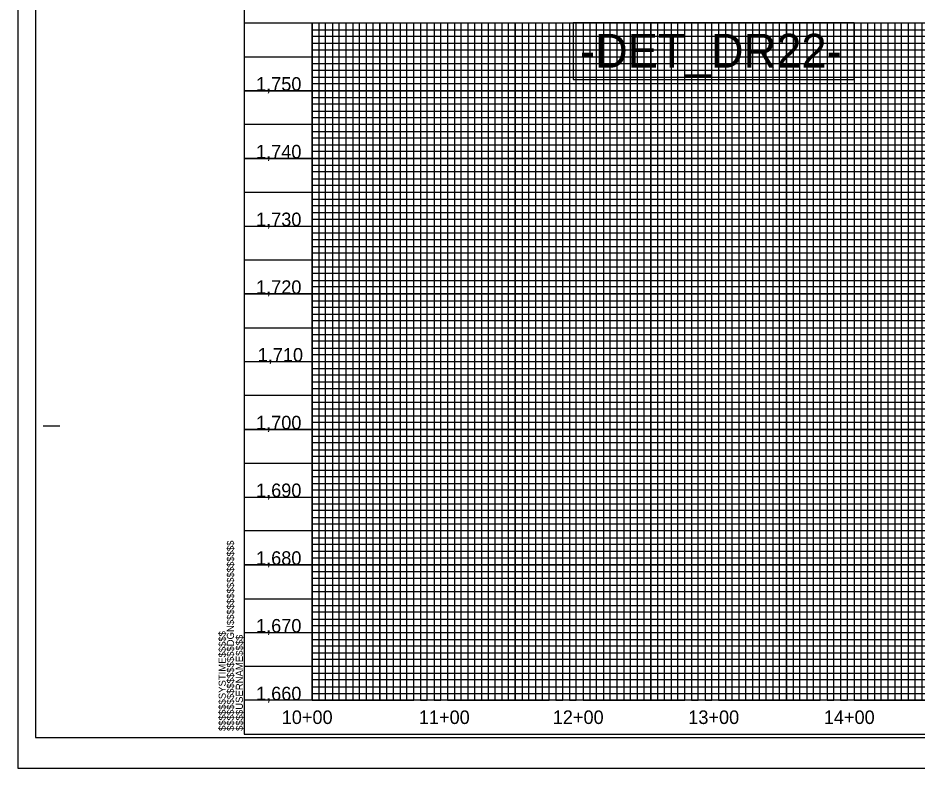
# Model space of a CAD drawing. Extents: x 505692 to 527456, y 415959 to 439886.
# Drawn here: x 505692 to 506355, y 438761 to 439315 of the extents above; entities that cross this region are included whole.
import ezdxf

# ---------------------------------------------------------------- set-up
doc = ezdxf.new("R2010")
doc.units = 0
for name, color, linetype in [('Exist Vertical Profile Vertical Axis Label', 7, 'Continuous'), ('Old_Level_1', 7, 'Continuous'), ('Prop Grid Mask', 7, 'Continuous'), ('Sheet Cutting Line CELL', 7, 'Continuous'), ('Sheet DOT Grid CELL', 7, 'Continuous'), ('Sheet Layout Profile Border Port 2', 7, 'Continuous'), ('Sheet Plot Border Inside CELL', 7, 'Continuous'), ('Sheet Plot Border Outside CELL', 7, 'Continuous'), ('Sheet Profile CELL', 7, 'Continuous'), ('Sheet Profile Grid Major CELL', 7, 'Continuous'), ('Sheet Profile Grid Middle CELL', 7, 'Continuous'), ('Sheet Profile Grid Minor CELL', 7, 'Continuous')]:
    doc.layers.add(name, color=color, linetype=linetype)

msp = doc.modelspace()

# ---------------------------------------------------------------- linework, layer by layer
at = {"layer": 'Prop Grid Mask'}
msp.add_lwpolyline([(506308.68, 439311.14), (506101.43, 439311.14), (506101.43, 439269.44), (506308.68, 439269.44)], close=True, dxfattribs=at)
at = {"layer": 'Sheet Cutting Line CELL'}
for p, q in [((505691.68, 439861.14), (505691.68, 438761.14)), ((505691.68, 438761.14), (507375.68, 438761.14))]:
    msp.add_line(p, q, dxfattribs=at)
at = {"layer": 'Sheet DOT Grid CELL'}
for p, q in [((505858.68, 439311.14), (507358.56, 439311.14)), ((505908.68, 439311.14), (505908.68, 438811.14)), ((505958.68, 439311.14), (505958.68, 438811.14)), ((506008.68, 439311.14), (506008.68, 438811.14)), ((506058.68, 439311.14), (506058.68, 438811.14)), ((506108.68, 439311.14), (506108.68, 438811.14)), ((506158.68, 439311.14), (506158.68, 438811.14)), ((506208.68, 439311.14), (506208.68, 438811.14)), ((506258.68, 439311.14), (506258.68, 438811.14)), ((506308.68, 439311.14), (506308.68, 438811.14)), ((505858.68, 439261.14), (507358.56, 439261.14)), ((505858.68, 439211.14), (507358.56, 439211.14)), ((505858.68, 439161.14), (507358.56, 439161.14)), ((505858.68, 439111.14), (507358.56, 439111.14)), ((505858.68, 439061.14), (507358.56, 439061.14)), ((505858.68, 439011.14), (507358.56, 439011.14)), ((505858.68, 438961.14), (507358.56, 438961.14)), ((505858.68, 438911.14), (507358.56, 438911.14)), ((505858.68, 438861.14), (507358.56, 438861.14))]:
    msp.add_line(p, q, dxfattribs=at)
at = {"layer": 'Sheet Layout Profile Border Port 2'}
msp.add_lwpolyline([(505908.68, 439311.14), (506358.68, 439311.14), (506358.68, 438811.14), (505908.68, 438811.14)], close=True, dxfattribs=at)
at = {"layer": 'Sheet Plot Border Inside CELL'}
msp.add_lwpolyline([(505704.68, 438783.59), (507371.18, 438783.59), (507371.18, 439838.69), (505704.68, 439838.69)], close=True, dxfattribs=at)
at = {"layer": 'Sheet Plot Border Outside CELL'}
msp.add_lwpolyline([(505691.68, 438761.14), (507375.68, 438761.14), (507375.68, 439861.14), (505691.68, 439861.14)], close=True, dxfattribs=at)
at = {"layer": 'Sheet Profile CELL'}
for p, q in [((505858.68, 439311.14), (507358.68, 439311.14)), ((505710.18, 439013.64), (505722.68, 439013.64)), ((507358.68, 438811.14), (505858.68, 438811.14)), ((505858.68, 438786.14), (507358.68, 438786.14)), ((505858.68, 438786.14), (505858.68, 438786.14)), ((505858.68, 438786.14), (505858.68, 438786.14)), ((505858.68, 438786.14), (505858.68, 438786.14)), ((505858.68, 438786.14), (505858.68, 438786.14)), ((505858.68, 438786.14), (505858.68, 438786.14)), ((505858.68, 438786.14), (505858.68, 438786.14)), ((505858.68, 438786.14), (505858.68, 438786.14))]:
    msp.add_line(p, q, dxfattribs=at)
msp.add_lwpolyline([(507358.68, 439836.14), (505858.68, 439836.14), (505858.68, 438786.14), (507358.68, 438786.14)], close=True, dxfattribs=at)
msp.add_lwpolyline([(505896.18, 438786.14), (505896.18, 438786.14)], dxfattribs=at)
at = {"layer": 'Sheet Profile Grid Major CELL'}
msp.add_line((505858.68, 438811.14), (505858.68, 438811.14), dxfattribs=at)
for points in [[(505908.68, 439311.14), (505908.68, 438811.14), (505958.68, 438811.14), (505958.68, 439311.14), (506008.68, 439311.14), (506008.68, 438811.14), (506058.68, 438811.14), (506058.68, 439311.14), (506108.68, 439311.14), (506108.68, 438811.14), (506158.68, 438811.14), (506158.68, 439311.14), (506208.68, 439311.14), (506208.68, 438811.14), (506258.68, 438811.14), (506258.68, 439311.14), (506308.68, 439311.14), (506308.68, 438811.14), (506358.68, 438811.14)], [(507358.68, 439261.14), (505858.68, 439261.14)], [(507358.68, 439211.14), (505858.68, 439211.14), (505858.68, 439161.14), (507358.68, 439161.14)], [(507358.68, 439111.14), (505858.68, 439111.14), (505858.68, 439061.14), (507358.68, 439061.14)], [(507358.68, 439011.14), (505858.68, 439011.14), (505858.68, 438961.14), (507358.68, 438961.14)], [(507358.68, 438911.14), (505858.68, 438911.14), (505858.68, 438911.14), (505858.68, 438861.14), (507358.68, 438861.14)], [(507358.68, 438811.14), (505858.68, 438811.14)]]:
    msp.add_lwpolyline(points, dxfattribs=at)
at = {"layer": 'Sheet Profile Grid Middle CELL'}
for points in [[(505883.68, 439311.14), (505933.68, 439311.14), (505933.68, 438811.14), (505983.68, 438811.14), (505983.68, 439311.14), (506033.68, 439311.14), (506033.68, 438811.14), (506083.68, 438811.14), (506083.68, 439311.14), (506133.68, 439311.14), (506133.68, 438811.14), (506183.68, 438811.14), (506183.68, 439311.14), (506233.68, 439311.14), (506233.68, 438811.14), (506283.68, 438811.14), (506283.68, 439311.14), (506333.68, 439311.14), (506333.68, 438811.14), (506383.68, 438811.14)], [(505858.68, 439286.14), (507358.68, 439286.14)], [(507358.68, 439236.14), (505858.68, 439236.14), (505858.68, 439186.14), (507358.68, 439186.14)], [(507358.68, 439136.14), (505858.68, 439136.14), (505858.68, 439086.14), (507358.68, 439086.14)], [(507358.68, 439036.14), (505858.68, 439036.14), (505858.68, 438986.14), (507358.68, 438986.14)], [(507358.68, 438936.14), (505858.68, 438936.14), (505858.68, 438886.14), (507358.68, 438886.14)], [(507358.68, 438836.14), (505858.68, 438836.14)]]:
    msp.add_lwpolyline(points, dxfattribs=at)
at = {"layer": 'Sheet Profile Grid Minor CELL'}
for p, q in [((505908.68, 439306.14), (507308.68, 439306.14)), ((507308.68, 439301.14), (505908.68, 439301.14)), ((505908.68, 439301.14), (505908.68, 439301.14)), ((505908.68, 439296.14), (507308.68, 439296.14)), ((507308.68, 439291.14), (505908.68, 439291.14)), ((505908.68, 439281.14), (507308.68, 439281.14)), ((507308.68, 439276.14), (505908.68, 439276.14)), ((505908.68, 439271.14), (507308.68, 439271.14)), ((507308.68, 439266.14), (505908.68, 439266.14)), ((505908.68, 439256.14), (507308.68, 439256.14)), ((507308.68, 439251.14), (505908.68, 439251.14)), ((505908.68, 439246.14), (507308.68, 439246.14)), ((507308.68, 439241.14), (505908.68, 439241.14)), ((505908.68, 439231.14), (507308.68, 439231.14)), ((507308.68, 439226.14), (505908.68, 439226.14)), ((505908.68, 439221.14), (507308.68, 439221.14)), ((507308.68, 439216.14), (505908.68, 439216.14)), ((505908.68, 439206.14), (507308.68, 439206.14)), ((507308.68, 439201.14), (505908.68, 439201.14)), ((505908.68, 439196.14), (507308.68, 439196.14)), ((507308.68, 439191.14), (505908.68, 439191.14)), ((505908.68, 439181.14), (507308.68, 439181.14)), ((507308.68, 439176.14), (505908.68, 439176.14)), ((505908.68, 439171.14), (507308.68, 439171.14)), ((507308.68, 439166.14), (505908.68, 439166.14)), ((505908.68, 439156.14), (507308.68, 439156.14)), ((507308.68, 439151.14), (505908.68, 439151.14)), ((505908.68, 439146.14), (507308.68, 439146.14)), ((507308.68, 439141.14), (505908.68, 439141.14)), ((505908.68, 439131.14), (507308.68, 439131.14)), ((507308.68, 439126.14), (505908.68, 439126.14)), ((505908.68, 439121.14), (507308.68, 439121.14)), ((507308.68, 439116.14), (505908.68, 439116.29)), ((505908.68, 439106.14), (507308.68, 439106.14)), ((507308.68, 439101.14), (505908.68, 439101.14)), ((505908.68, 439096.14), (507308.68, 439096.14)), ((507308.68, 439091.14), (505908.68, 439091.14)), ((505908.68, 439081.14), (507308.68, 439081.14)), ((507308.68, 439076.14), (505908.68, 439076.14)), ((505908.68, 439071.14), (507308.68, 439071.14)), ((507308.68, 439066.14), (505908.68, 439066.14)), ((505908.68, 439056.14), (507308.68, 439056.14)), ((507308.68, 439051.14), (505908.68, 439051.14)), ((505908.68, 439046.14), (507308.68, 439046.14)), ((507308.68, 439041.14), (505908.68, 439041.14)), ((505908.68, 439031.14), (507308.68, 439031.14)), ((507308.68, 439026.14), (505908.68, 439026.14)), ((505908.68, 439021.14), (507308.68, 439021.14)), ((507308.68, 439016.14), (505908.68, 439016.14)), ((505908.68, 439006.14), (507308.68, 439006.14)), ((507308.68, 439001.14), (505908.68, 439001.14)), ((505908.68, 438996.14), (507308.68, 438996.14)), ((507308.68, 438991.14), (505908.68, 438991.14)), ((505908.68, 438981.14), (507308.68, 438981.14)), ((507308.68, 438976.14), (505908.68, 438976.14)), ((505908.68, 438971.14), (507308.68, 438971.14)), ((507308.68, 438966.14), (505908.68, 438966.14)), ((505908.68, 438956.14), (507308.68, 438956.14)), ((507308.68, 438951.14), (505908.68, 438951.14)), ((505908.68, 438946.14), (507308.68, 438946.14)), ((507308.68, 438941.14), (505908.68, 438941.14)), ((505908.68, 438931.14), (507308.68, 438931.14)), ((507308.68, 438926.14), (505908.68, 438926.14)), ((505908.68, 438921.14), (507308.68, 438921.14)), ((507308.68, 438916.14), (505908.68, 438916.14)), ((505908.68, 438906.14), (507308.68, 438906.14)), ((507308.68, 438901.14), (505908.68, 438901.14)), ((505908.68, 438896.14), (507308.68, 438896.14)), ((507308.68, 438891.14), (505908.68, 438891.14)), ((505908.68, 438881.14), (507308.68, 438881.14)), ((507308.68, 438876.14), (505908.68, 438876.14)), ((505908.68, 438871.14), (507308.68, 438871.14)), ((507308.68, 438866.14), (505908.68, 438866.14)), ((505908.68, 438856.14), (507308.68, 438856.14)), ((507308.68, 438851.14), (505908.68, 438851.14)), ((505908.68, 438846.14), (507308.68, 438846.14)), ((507308.68, 438841.14), (505908.68, 438841.14)), ((505908.68, 438831.14), (507308.68, 438831.14)), ((507308.68, 438826.14), (505908.68, 438826.14)), ((505908.68, 438821.14), (507308.68, 438821.14)), ((505908.68, 438816.14), (507308.68, 438816.14))]:
    msp.add_line(p, q, dxfattribs=at)
for points in [[(505908.68, 439311.14), (505913.68, 439311.14), (505913.68, 438811.14), (505918.68, 438811.14), (505918.68, 439311.14), (505923.68, 439311.14), (505923.68, 438811.14), (505928.68, 438811.14), (505928.68, 439311.14), (505938.68, 439311.14), (505938.68, 438811.14), (505943.68, 438811.14), (505943.68, 439311.14), (505948.68, 439311.14), (505948.68, 438811.14), (505953.68, 438811.14), (505963.68, 438811.14), (505968.68, 438811.14), (505968.68, 439311.14), (505973.68, 439311.14), (505973.68, 438811.14), (505978.68, 438811.14), (505978.68, 439311.14), (505988.68, 439311.14), (505988.68, 438811.14), (505993.68, 438811.14), (505993.68, 439311.14), (505998.68, 439311.14), (505998.68, 438811.14), (506003.68, 438811.14), (506003.68, 439311.14), (506013.68, 439311.14), (506013.68, 438811.14), (506018.68, 438811.14), (506018.68, 439311.14), (506023.68, 439311.14), (506023.68, 438811.14), (506028.68, 438811.14), (506028.68, 439311.14), (506038.68, 439311.14), (506038.68, 438811.14), (506043.68, 438811.14), (506043.68, 439311.14), (506048.68, 439311.14), (506048.68, 438811.14), (506053.68, 438811.14), (506053.68, 439311.14), (506063.68, 439311.14), (506063.68, 438811.14), (506068.68, 438811.14), (506068.68, 439311.14), (506073.68, 439311.14), (506073.68, 438811.14), (506078.68, 438811.14), (506078.68, 439311.14), (506088.68, 439311.14), (506088.68, 438811.14), (506093.68, 438811.14), (506093.68, 439311.14), (506098.68, 439311.14), (506098.68, 438811.14), (506103.68, 438811.14), (506103.68, 439311.14), (506113.68, 439311.14), (506113.68, 438811.14), (506118.68, 438811.14), (506118.68, 439311.14), (506123.68, 439311.14), (506123.68, 438811.14)], [(505953.68, 438811.14), (505953.68, 439311.14), (505963.68, 439311.14), (505963.68, 438811.14)], [(506123.68, 438811.14), (506128.68, 438811.14), (506128.68, 439311.14), (506138.68, 439311.14), (506138.68, 438811.14), (506143.68, 438811.14), (506143.68, 439311.14), (506148.68, 439311.14), (506148.68, 438811.14), (506153.68, 438811.14), (506153.68, 439311.14), (506163.68, 439311.14), (506163.68, 438811.14), (506168.68, 438811.14), (506168.68, 439311.14), (506173.68, 439311.14), (506173.68, 438811.14), (506178.68, 438811.14), (506178.68, 439311.14), (506188.68, 439311.14), (506188.68, 438811.14), (506193.68, 438811.14), (506193.68, 439311.14), (506198.68, 439311.14), (506198.68, 438811.14), (506203.68, 438811.14), (506203.68, 439311.14), (506213.68, 439311.14), (506213.68, 438811.14), (506218.68, 438811.14), (506218.68, 439311.14), (506223.68, 439311.14), (506223.68, 438811.14), (506228.68, 438811.14), (506228.68, 439311.14), (506238.68, 439311.14), (506238.68, 438811.14), (506243.68, 438811.14), (506243.68, 439311.14), (506248.68, 439311.14), (506248.68, 438811.14), (506253.68, 438811.14), (506253.68, 439311.14), (506263.68, 439311.14), (506263.68, 438811.14), (506268.68, 438811.14), (506268.68, 439311.14), (506273.68, 439311.14), (506273.68, 438811.14), (506278.68, 438811.14), (506278.68, 439311.14), (506288.68, 439311.14), (506288.68, 438811.14), (506293.68, 438811.14), (506293.68, 439311.14), (506298.68, 439311.14), (506298.68, 438811.14), (506303.68, 438811.14), (506303.68, 439311.14), (506313.68, 439311.14), (506313.68, 438811.14), (506318.68, 438811.14), (506318.68, 439311.14), (506323.68, 439311.14), (506323.68, 438811.14), (506328.68, 438811.14), (506328.68, 439311.14), (506338.68, 439311.14), (506338.68, 438811.14), (506343.68, 438811.14), (506343.68, 439311.14), (506348.68, 439311.14), (506348.68, 438811.14), (506353.68, 438811.14), (506353.68, 439311.14), (506363.68, 439311.14)]]:
    msp.add_lwpolyline(points, dxfattribs=at)

# ---------------------------------------------------------------- texts
at = {"layer": 'Exist Vertical Profile Vertical Axis Label'}
for s, p in [('1,750', (505867.37, 439261.14)), ('1,740', (505867.37, 439211.14)), ('1,730', (505867.37, 439161.14)), ('1,720', (505867.37, 439111.14)), ('1,710', (505868.57, 439061.14)), ('1,700', (505867.37, 439011.14)), ('1,690', (505867.37, 438961.14)), ('1,680', (505867.37, 438911.14)), ('1,670', (505867.37, 438861.14)), ('1,660', (505867.37, 438811.14)), ('10+00', (505886.3, 438793.64)), ('11+00', (505987.49, 438793.64)), ('12+00', (506086.3, 438793.64)), ('13+00', (506186.3, 438793.64)), ('14+00', (506286.3, 438793.64))]:
    msp.add_text(s, height=10, dxfattribs=at).set_placement(p)
at = {"layer": 'Old_Level_1'}
msp.add_text('-DET_DR22-', height=25, dxfattribs=at).set_placement((506106.33, 439278.11))
at = {"layer": 'Sheet Profile CELL'}
for s, p in [('$$$$$$$$$$$$$$$$DGN$$$$$$$$$$$$$$$$', (505851.04, 438788.52)), ('$$$$$$SYSTIME$$$$$', (505844.99, 438788.52)), ('$$$$USERNAME$$$$', (505857.62, 438788.53))]:
    msp.add_text(s, height=5.25, rotation=90, dxfattribs=at).set_placement(p)

doc.saveas('drawing.dxf')
